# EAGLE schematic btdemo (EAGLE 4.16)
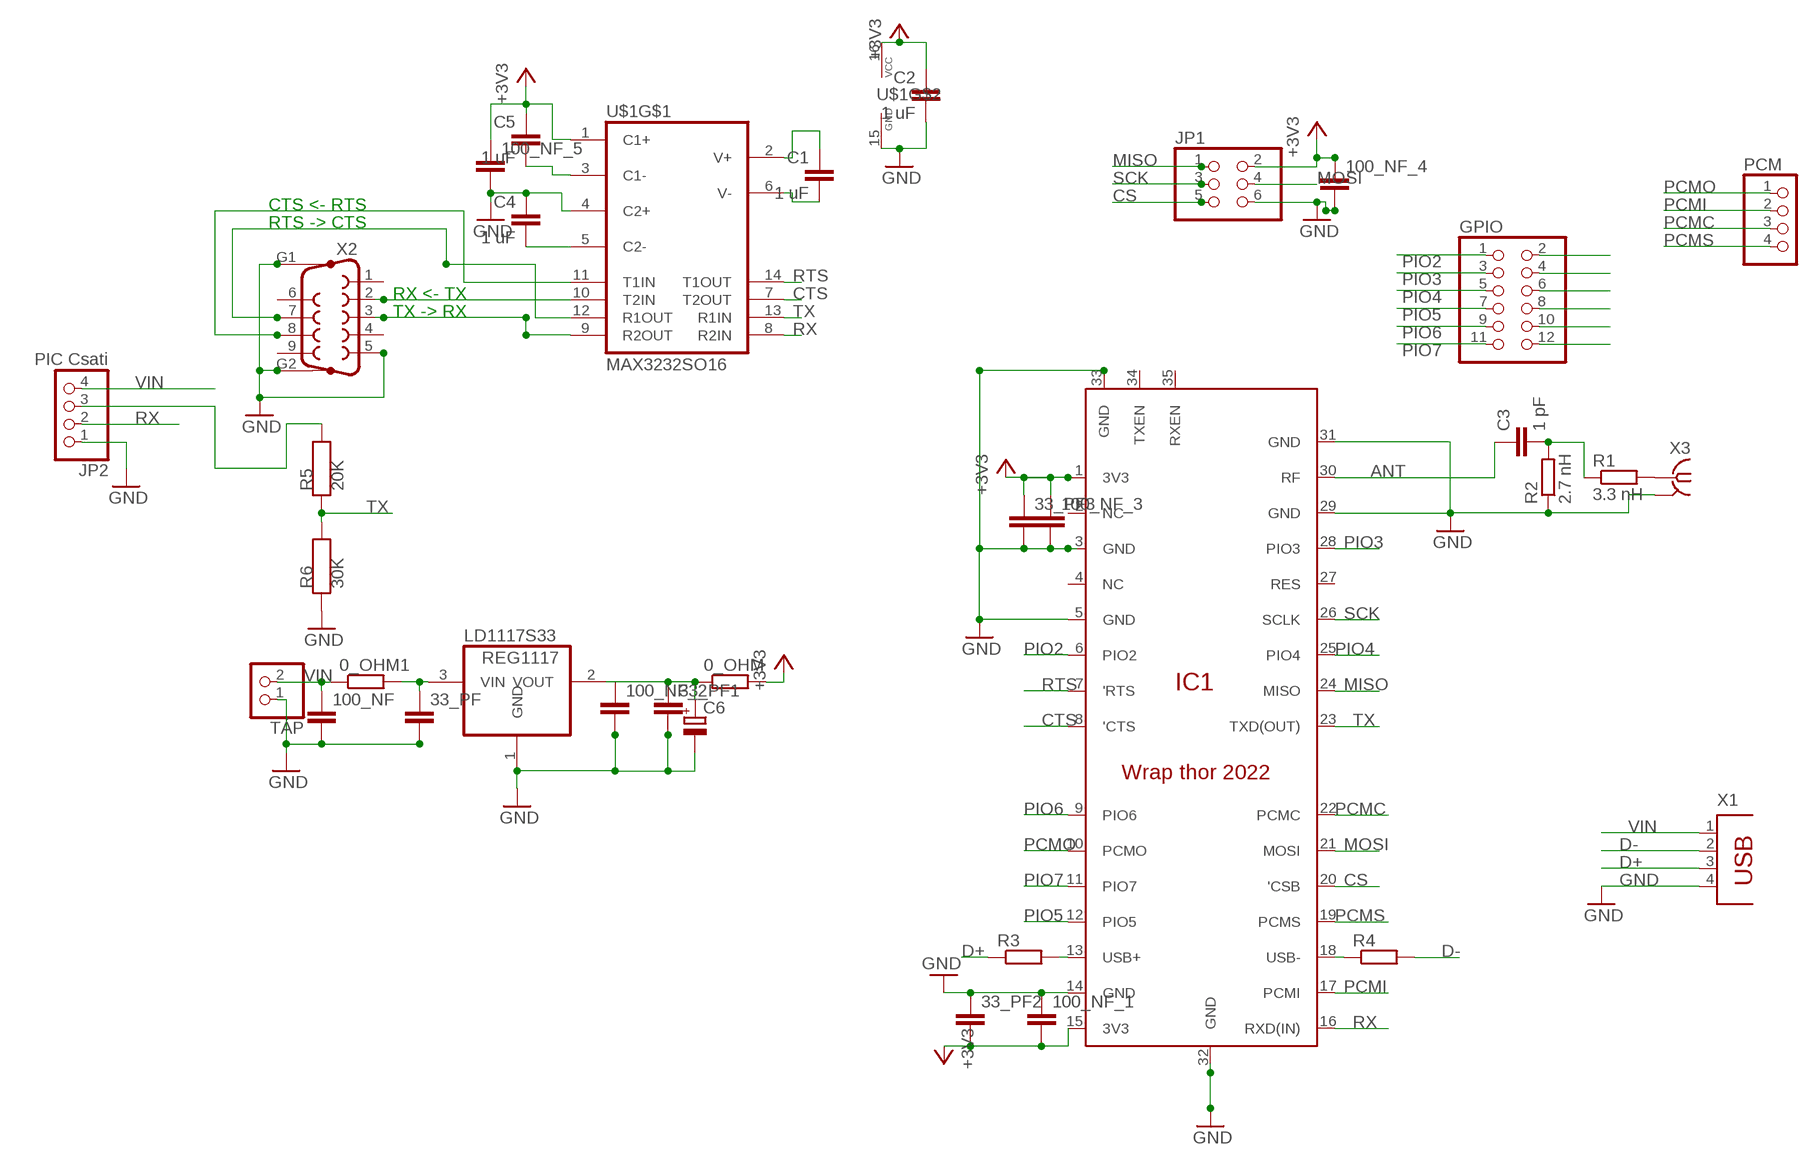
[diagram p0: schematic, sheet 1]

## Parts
0_OHM  R-R0805  [R0805]
0_OHM1  R-R0805  [R0805]
33_PF  C-EUC0805K  [C0805K]
33_PF1  C-EUC0805K  [C0805K]
33_PF2  C-EUC0805K  [C0805K]
33_PF3  C-EUC0805K  [C0805K]
100_NF  C-EUC0805K  [C0805K]
100_NF_1  C-EUC0805K  [C0805K]
100_NF_2  C-EUC0805K  [C0805K]
100_NF_3  C-EUC0805K  [C0805K]
100_NF_4  C-EUC0805K  [C0805K]
100_NF_5  C-EUC0805K  [C0805K]
C1  1 uF  C-EUC0603  [C0603]
C2  1 uF  C-EUC0603  [C0603]
C3  1 pF  C-EUC0805  [C0805]
C4  1 uF  C-EUC0603  [C0603]
C5  1 uF  C-EUC0603  [C0603]
C6  CPOL-EUE2.5-5  [E2,5-5]
GPIO  PINHD-2X6  [2X06]
IC1  WRAPTHOR_2022-1  [WRAPTHOR_2022-1]
JP1  PINHD-2X3  [2X03]
JP2  PIC Csati  PINHD-1X4  [1X04]
LD1117S33  REG1117  [SOT223]
PCM  PINHD-1X4  [1X04]
R1  3.3 nH  R-EU_R0805  [R0805]
R2  2.7 nH  R-EU_R0805  [R0805]
R3  R-EU_R0805  [R0805]
R4  R-EU_R0805  [R0805]
R5  20K  RES-0805  [0805]
R6  30K  RES-0805  [0805]
TÁP  PINHD-1X2  [1X02]
U$1  MAX3232SO16  [SO16]
X1  PN61729  [PN61729]
X2  F09HP  [F09HP]
X3  BU-SMA-G  [BU-SMA-G]

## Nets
+3V3: 0_OHM.2 33_PF2.2 33_PF3.1 100_NF_1.2 100_NF_3.1 100_NF_4.1 100_NF_5.1 C2.1 C5.1 IC1.1(3V3) IC1.15(3V3) JP1.2 U$1.1(C1+) U$1.16(VCC)
ANT: C3.1 IC1.30(RF)
CS: IC1.20('CSB) JP1.5
CTS: IC1.8('CTS) U$1.7(T2OUT)
D+: R3.1 X1.3
D-: R4.2 X1.2
GND: 33_PF1.2 33_PF2.1 33_PF3.2 33_PF.2 100_NF.2 100_NF_1.1 100_NF_2.2 100_NF_3.2 100_NF_4.2 100_NF_5.2 C2.2 C4.1 C6.- IC1.3(GND) IC1.5(GND) IC1.14(GND) IC1.29(GND) IC1.31(GND) IC1.32(GND) IC1.33(GND) JP1.6 JP2.1 LD1117S33.1(GND) R2.1 R6.P$1 TÁP.1 U$1.4(C2+) U$1.15(GND) X1.4 X2.5 X2.G1 X2.G2 X3.2(GND)
MISO: IC1.24(MISO) JP1.1
MOSI: IC1.21(MOSI) JP1.4
N$1: C1.1 U$1.2(V+)
N$2: C1.2 U$1.6(V-)
N$5: U$1.10(T2IN) X2.2
N$6: U$1.9(R2OUT) X2.3
N$7: C4.2 U$1.5(C2-)
N$8: C5.2 U$1.3(C1-)
N$9: IC1.18(USB-) R4.1
N$10: U$1.12(R1OUT) X2.7
N$11: U$1.11(T1IN) X2.8
N$12: 0_OHM1.2 33_PF.1 LD1117S33.3(VIN)
N$13: 0_OHM.1 33_PF1.1 100_NF_2.1 C6.+ LD1117S33.2(VOUT)
N$14: IC1.13(USB+) R3.2
N$15: R1.2 X3.1
N$16: C3.2 R1.1 R2.2
N$17: JP2.3 R5.P$2
PCMC: IC1.22(PCMC) PCM.3
PCMI: IC1.17(PCMI) PCM.2
PCMO: IC1.10(PCMO) PCM.1
PCMS: IC1.19(PCMS) PCM.4
PIO2: GPIO.1 GPIO.2 IC1.6(PIO2)
PIO3: GPIO.3 GPIO.4 IC1.28(PIO3)
PIO4: GPIO.5 GPIO.6 IC1.25(PIO4)
PIO5: GPIO.7 GPIO.8 IC1.12(PIO5)
PIO6: GPIO.9 GPIO.10 IC1.9(PIO6)
PIO7: GPIO.11 GPIO.12 IC1.11(PIO7)
RTS: IC1.7('RTS) U$1.14(T1OUT)
RX: IC1.16(RXD(IN)) JP2.2 U$1.8(R2IN)
SCK: IC1.26(SCLK) JP1.3
TX: IC1.23(TXD(OUT)) R5.P$1 R6.P$2 U$1.13(R1IN)
VIN: 0_OHM1.1 100_NF.1 JP2.4 TÁP.2 X1.1
Unconnected: IC1.2(NC) IC1.4(NC) IC1.27(RES) IC1.34(TXEN) IC1.35(RXEN) X2.1 X2.4 X2.6 X2.9

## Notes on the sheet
- CTS <- RTS
- RTS -> CTS
- RX <- TX
- TX -> RX

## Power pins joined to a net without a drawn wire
GND: X3.3(GND) X3.4(GND) X3.5(GND)

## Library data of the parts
0_OHM 0_OHM1 = quantum-sensor:R: Resistor
33_PF 33_PF1-33_PF3 100_NF 100_NF_1-100_NF_5 C1-C5 = rcl:C-EU: CAPACITOR, European symbol
C6 = rcl:CPOL-EU: POLARIZED CAPACITOR, European symbol
GPIO = pinhead:PINHD-2X6: PIN HEADER
IC1 = bluegiga:WRAPTHOR_2022-1
JP1 = pinhead:PINHD-2X3: PIN HEADER
JP2 PCM = pinhead:PINHD-1X4: PIN HEADER
LD1117S33 = burr-brown:REG1117: 800mA and 1A Low Dropout (LDO) Positive Regulator 1.8V, 2.5V, 2.85V, 3.3V, 5V, and Adj
R1-R4 = rcl:R-EU_: RESISTOR, European symbol
R5 R6 = scenix4:RES-0805
TÁP = pinhead:PINHD-1X2: PIN HEADER
U$1 = maxim-7a:MAX3232SO16
X1 = con-berg:PN61729: BERG USB connector
X2 = con-subd:F09HP: SUB-D
X3 = con-coax:BU-SMA-G: FEMALE SMA CONNECTOR Radiall distributor RS 193-9117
